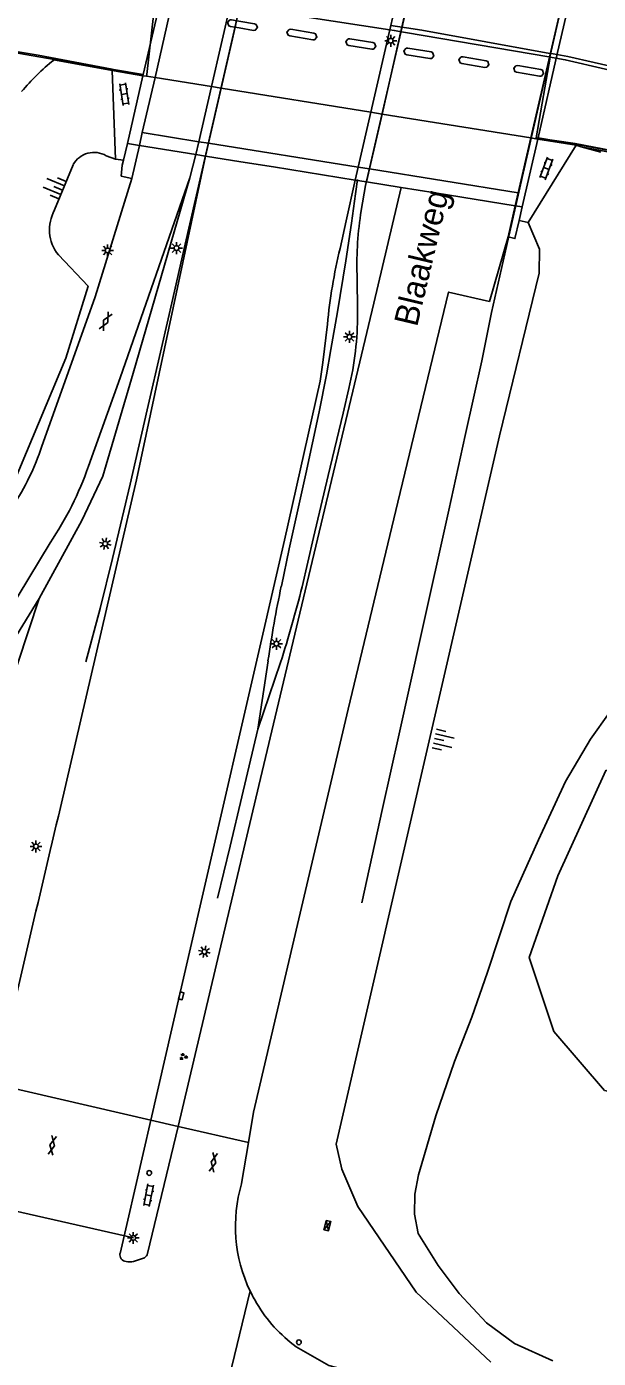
# Model space of a CAD drawing. Extents: x 131000 to 133013, y 393000 to 396501.
# Drawn here: x 131420.7 to 131480.6, y 394396 to 394535.6 of the extents above; entities that cross this region are included whole.
import ezdxf

# ---------------------------------------------------------------- set-up
doc = ezdxf.new("R2010")
doc.units = 0
for name, color, linetype in [('gg-anno-openbare ruimte label', 7, 'Continuous'), ('gg-knt-BGT kruinlijn', 7, 'Continuous'), ('gg-knt-bovenkant onderkant talud', 7, 'Continuous'), ('gg-knt-bronhoudergrens', 7, 'Continuous'), ('gg-knt-verharding', 7, 'Continuous'), ('gg-knt-verharding niveau 01', 7, 'Continuous'), ('gg-knt-verharding nz', 7, 'Continuous'), ('gg-kwrk-duiker nz buis', 7, 'Continuous'), ('gg-kwrk-kunstwerk', 7, 'Continuous'), ('gg-kwrk-kunstwerk niveau 01', 7, 'Continuous'), ('gt-grn-groengrens', 7, 'Continuous'), ('gt-grn-weggrens', 7, 'Continuous'), ('gt-knt-geleideconstructie', 7, 'Continuous'), ('gt-knt-lijn portaal', 7, 'Continuous'), ('gt-symb-gesloten verharding', 7, 'Continuous'), ('gt-symb-groenvak', 7, 'Continuous'), ('gt-symb-klinker verharding', 7, 'Continuous'), ('gt-symb-kolk', 7, 'Continuous'), ('gt-symb-lichtmast', 7, 'Continuous'), ('gt-symb-talud symbool', 7, 'Continuous'), ('gt-symb-verkeersregelinstallatiekast', 7, 'Continuous'), ('gt-symb-verkeersregelinstallatiepaal', 7, 'Continuous'), ('gx-grn-maaiveld', 7, 'Continuous')]:
    doc.layers.add(name, color=color, linetype=linetype)

# ---------------------------------------------------------------- blocks, each defined once
blk = doc.blocks.new('gt0-LMAST')
at = {"layer": 'gt-symb-lichtmast'}
for p, q in [((-0.18, 0.17), (-0.45, 0.44)), ((-0.01, 0.25), (-0.01, 0.62)), ((0.17, 0.17), (0.44, 0.44)), ((-0.26, 0), (-0.63, 0)), ((-0.18, -0.18), (-0.45, -0.45)), ((-0.01, -0.25), (-0.01, -0.63)), ((0.44, -0.45), (0.17, -0.18)), ((0.24, 0), (0.62, 0))]:
    blk.add_line(p, q, dxfattribs=at)
blk.add_circle((-0.01, 0), 0.25, dxfattribs=at)
blk = doc.blocks.new('gt0-KL1')
at = {"layer": 'gt-symb-klinker verharding'}
for p, q in [((-1.15, 0.3), (1.15, 0.3)), ((-1, -0.3), (-1, 0.3)), ((-0.5, 0.3), (-0.5, 0.45)), ((0, -0.3), (0, 0.3)), ((0.5, 0.3), (0.5, 0.45)), ((1, -0.3), (1, 0.3)), ((-1.15, -0.3), (1.15, -0.3)), ((-0.5, -0.45), (-0.5, -0.3)), ((0.5, -0.45), (0.5, -0.3))]:
    blk.add_line(p, q, dxfattribs=at)
blk = doc.blocks.new('gt0-GESVH1')
at = {"layer": 'gt-symb-gesloten verharding'}
for p, q in [((-0.99, -0.26), (0.01, 0.24)), ((0.01, -0.26), (-0.99, 0.24)), ((0.01, 0.24), (1.01, -0.26)), ((1.01, 0.24), (0.01, -0.26))]:
    blk.add_line(p, q, dxfattribs=at)
blk = doc.blocks.new('gt0-TALUD_1')
at = {"layer": 'gt-symb-talud symbool'}
for p, q in [((-1, -1), (-1, 0)), ((-0.5, -2), (-0.5, 0)), ((0, -1), (0, 0)), ((0.5, -2), (0.5, 0)), ((1, -1), (1, 0))]:
    blk.add_line(p, q, dxfattribs=at)
blk = doc.blocks.new('gt0-VIPAAL')
at = {"layer": 'gt-symb-verkeersregelinstallatiepaal'}
blk.add_circle((0, 0), 0.25, dxfattribs=at)
blk = doc.blocks.new('gt0-VRIKST')
at = {"layer": 'gt-symb-verkeersregelinstallatiekast'}
for p, q in [((-0.5, -0.25), (0.5, 0.25)), ((-0.5, 0.25), (0.5, -0.25))]:
    blk.add_line(p, q, dxfattribs=at)
blk.add_lwpolyline([(0.5, 0.25), (-0.5, 0.25), (-0.5, -0.25), (0.5, -0.25)], close=True, dxfattribs=at)
blk = doc.blocks.new('gt0-GRVAK')
at = {"layer": 'gt-symb-groenvak'}
for p, q in [((-0.11, 0.19), (-0.23, 0.24)), ((-0.18, 0.15), (0.09, 0.15)), ((-0.09, 0.21), (-0.16, 0.32)), ((-0.05, 0.21), (-0.05, 0.39)), ((0, 0.21), (0.06, 0.32)), ((0.02, 0.19), (0.13, 0.24)), ((0.26, -0.05), (0.2, 0.06)), ((0.31, -0.05), (0.31, 0.13)), ((0.35, -0.05), (0.41, 0.06)), ((-0.24, -0.23), (-0.36, -0.18)), ((-0.32, -0.26), (-0.05, -0.26)), ((-0.23, -0.21), (-0.29, -0.09)), ((-0.18, -0.2), (-0.18, -0.02)), ((-0.14, -0.21), (-0.07, -0.09)), ((-0.12, -0.23), (0, -0.18)), ((0.24, -0.07), (0.12, -0.02)), ((0.17, -0.11), (0.44, -0.11)), ((0.37, -0.07), (0.49, -0.02))]:
    blk.add_line(p, q, dxfattribs=at)
blk = doc.blocks.new('gt0-KOLK')
at = {"layer": 'gt-symb-kolk'}
blk.add_lwpolyline([(0, 0), (0.37, 0), (0.37, 0.4), (-0.38, 0.4), (-0.38, 0), (0, 0)], dxfattribs=at)

msp = doc.modelspace()

# ---------------------------------------------------------------- linework, layer by layer
at = {"layer": 'gg-knt-BGT kruinlijn'}
for p, q in [((131429.05, 394522.08), (131430.04, 394521.73)), ((131423.65, 394516.39), (131425.6, 394521.14)), ((131470.29, 394492.7), (131453.14, 394418.48)), ((131422.02, 394475.65), (131412.64, 394447.29)), ((131469.38, 394395.62), (131461.54, 394402.95))]:
    msp.add_line(p, q, dxfattribs=at)
for points in [[(131473.27, 394515.09), (131474.45, 394512.29), (131474.43, 394509.76), (131470.29, 394492.7)], [(131383.88, 394437.84), (131395.29, 394451.29), (131407.22, 394467.55), (131417.8, 394484.14), (131424.83, 394500.87), (131427.16, 394508.4), (131424.04, 394511.69)], [(131461.54, 394402.95), (131455.41, 394411.93), (131453.74, 394415.83), (131453.14, 394418.48)]]:
    msp.add_lwpolyline(points, dxfattribs=at)
for centre, radius, start, end in [((131427.78, 394519.94), 2.49, 59.2969, 151.084), ((131427.34, 394514.33), 4.23, 150.8617, 218.6757)]:
    msp.add_arc(centre, radius, start, end, dxfattribs=at)
at = {"layer": 'gg-knt-bovenkant onderkant talud'}
msp.add_line((131423.54, 394532.12), (131429.68, 394531), dxfattribs=at)
msp.add_lwpolyline([(131437.81, 394519.77), (131431.89, 394499.29), (131428.71, 394488.5), (131426.49, 394483.84), (131422.02, 394475.65)], dxfattribs=at)
msp.add_arc((131438.96, 394513.13), 24.45, 129.074, 140.1537, dxfattribs=at)
at = {"layer": 'gg-knt-bronhoudergrens'}
msp.add_lwpolyline([(131405.47, 394535.24), (131409.11, 394534.78), (131413.08, 394534.1), (131421.91, 394532.63), (131429.68, 394531.15), (131429.68, 394531)], dxfattribs=at)
at = {"layer": 'gg-knt-verharding'}
for p, q in [((131432.91, 394530.47), (131429.68, 394531)), ((131429.68, 394531), (131430.04, 394521.73)), ((131473.27, 394515.09), (131478.32, 394523.17)), ((131478.32, 394523.17), (131474.29, 394523.83)), ((131430.04, 394521.73), (131430.86, 394521.6)), ((131432.23, 394488.09), (131439.45, 394522.04)), ((131438.46, 394522.2), (131437.81, 394519.77)), ((131472.32, 394515.28), (131473.27, 394515.09)), ((131424.25, 394453.76), (131432.23, 394488.09)), ((131423.17, 394481.51), (131413.49, 394465.45)), ((131433.73, 394420.99), (131430.5, 394407.02)), ((131433.73, 394420.99), (131436.58, 394420.33)), ((131433.39, 394407.01), (131436.58, 394420.33)), ((131443.96, 394418.63), (131443.25, 394414.33)), ((131431.91, 394406.17), (131433.06, 394406.55))]:
    msp.add_line(p, q, dxfattribs=at)
for points in [[(131422.45, 394492.03), (131427.88, 394507.29), (131431.74, 394519.69)], [(131437.81, 394519.77), (131430.53, 394498.78), (131427.19, 394489.52)], [(131459.96, 394518.76), (131457.1, 394506.64), (131449.19, 394473.39), (131445.23, 394456.81), (131441.06, 394439.25), (131436.58, 394420.33)], [(131455.15, 394519.52), (131454.2, 394515.26), (131453.56, 394512.36)], [(131471.18, 394513.56), (131469.21, 394506.8), (131464.93, 394507.78), (131459.61, 394485.77), (131454.43, 394464.07), (131449.23, 394442.1), (131444.49, 394421.83), (131443.96, 394418.63)], [(131433.73, 394420.99), (131436.72, 394434.05), (131447.73, 394481.77), (131451.47, 394498.44), (131451.77, 394500.41), (131452.24, 394504.41)], [(131448.96, 394397.23), (131452.4, 394395.25), (131459.3, 394393.44)]]:
    msp.add_lwpolyline(points, dxfattribs=at)
for centre, radius, start, end in [((131508.14, 394499.17), 56.15, 166.4167, 174.6517), ((131397, 394500.04), 26.68, 327.4924, 342.5392), ((131395.02, 394500.65), 34.04, 325.7927, 340.9229), ((134415.36, 393744.36), 3074.08, 166.65758, 167.21315), ((131458.35, 394409.86), 15.75, 163.5297, 205.5356), ((131431.21, 394406.89), 0.727, 169.5914, 264.9801), ((131432.72, 394407.15), 0.681, 299.2665, 348.2912), ((131431.51, 394407.77), 1.65, 257.1884, 283.8656), ((131458.27, 394409.83), 15.66, 205.5256, 210.9341), ((131458.36, 394409.88), 15.77, 210.9484, 233.4006)]:
    msp.add_arc(centre, radius, start, end, dxfattribs=at)
at = {"layer": 'gg-knt-verharding niveau 01'}
for p, q in [((131458.84, 394535.58), (131461.6, 394547.61)), ((131462.77, 394547.42), (131460.01, 394535.4)), ((131442.13, 394538.13), (131440.1, 394529.32)), ((131441.09, 394529.16), (131442.56, 394535.56)), ((131442.56, 394535.56), (131442.71, 394536.24)), ((131456.79, 394526.64), (131458.84, 394535.58)), ((131460.01, 394535.4), (131457.96, 394526.45)), ((131440.1, 394529.32), (131438.77, 394523.55)), ((131439.76, 394523.39), (131441.09, 394529.16)), ((131455.46, 394520.88), (131456.79, 394526.64)), ((131457.96, 394526.45), (131456.64, 394520.69)), ((131438.77, 394523.55), (131438.46, 394522.2)), ((131439.45, 394522.04), (131439.76, 394523.39)), ((131455.15, 394519.52), (131455.46, 394520.88)), ((131456.64, 394520.69), (131456.32, 394519.34))]:
    msp.add_line(p, q, dxfattribs=at)
at = {"layer": 'gg-knt-verharding nz'}
for p, q in [((131434.17, 394530.27), (131440.1, 394529.32)), ((131440.1, 394529.32), (131441.09, 394529.16)), ((131441.09, 394529.16), (131456.79, 394526.64)), ((131456.79, 394526.64), (131457.96, 394526.45)), ((131457.96, 394526.45), (131473.57, 394523.95))]:
    msp.add_line(p, q, dxfattribs=at)
at = {"layer": 'gg-kwrk-duiker nz buis'}
for p, q in [((131405.04, 394535.33), (131423.61, 394532.17)), ((131423.61, 394532.17), (131432.93, 394530.58))]:
    msp.add_line(p, q, dxfattribs=at)
msp.add_lwpolyline([(131474.32, 394523.97), (131478.24, 394523.3), (131489.42, 394521.19)], dxfattribs=at)
at = {"layer": 'gg-kwrk-kunstwerk'}
for p, q in [((131438.77, 394523.55), (131432.84, 394524.5)), ((131431.27, 394523.35), (131430.86, 394521.6)), ((131432.53, 394523.15), (131431.74, 394519.69)), ((131439.76, 394523.39), (131438.77, 394523.55)), ((131455.46, 394520.88), (131439.76, 394523.39)), ((131456.64, 394520.69), (131455.46, 394520.88)), ((131472.24, 394518.19), (131456.64, 394520.69)), ((131471.18, 394513.56), (131471.93, 394516.84)), ((131472.65, 394516.72), (131472.32, 394515.28))]:
    msp.add_line(p, q, dxfattribs=at)
for points in [[(131431.74, 394519.69), (131430.63, 394519.95), (131430.74, 394521.08), (131430.86, 394521.6)], [(131472.32, 394515.28), (131471.89, 394513.4), (131471.18, 394513.56)]]:
    msp.add_lwpolyline(points, dxfattribs=at)
at = {"layer": 'gg-kwrk-kunstwerk niveau 01'}
for p, q in [((131475.66, 394533.01), (131478.39, 394544.86)), ((131479.1, 394544.74), (131476.37, 394532.9)), ((131434.8, 394538.68), (131432.93, 394530.58)), ((131435.66, 394536.76), (131434.17, 394530.27)), ((131473.57, 394523.95), (131475.66, 394533.01)), ((131476.37, 394532.9), (131474.29, 394523.83)), ((131432.91, 394530.47), (131431.27, 394523.35)), ((131434.17, 394530.27), (131432.84, 394524.5)), ((131432.93, 394530.58), (131432.91, 394530.47)), ((131432.84, 394524.5), (131432.53, 394523.15)), ((131432.53, 394523.15), (131431.27, 394523.35)), ((131438.46, 394522.2), (131432.53, 394523.15)), ((131472.24, 394518.19), (131473.57, 394523.95)), ((131474.29, 394523.83), (131472.65, 394516.72)), ((131439.45, 394522.04), (131438.46, 394522.2)), ((131443.18, 394521.44), (131439.45, 394522.04)), ((131446.6, 394520.9), (131443.18, 394521.44)), ((131455.15, 394519.52), (131446.6, 394520.9)), ((131456.32, 394519.34), (131455.15, 394519.52)), ((131459.96, 394518.76), (131456.32, 394519.34)), ((131463.53, 394518.18), (131459.96, 394518.76)), ((131471.93, 394516.84), (131463.53, 394518.18)), ((131471.93, 394516.84), (131472.24, 394518.19)), ((131471.93, 394516.84), (131472.65, 394516.72))]:
    msp.add_line(p, q, dxfattribs=at)
at = {"layer": 'gt-grn-groengrens'}
msp.add_lwpolyline([(131422.02, 394475.65), (131407.25, 394451.6), (131389.92, 394430.41), (131384.61, 394418.87)], dxfattribs=at)
at = {"layer": 'gt-grn-weggrens'}
for p, q in [((131433.73, 394420.99), (131417.51, 394424.73)), ((131436.58, 394420.33), (131443.96, 394418.63)), ((131444.14, 394403.08), (131439.96, 394385.76))]:
    msp.add_line(p, q, dxfattribs=at)
at = {"layer": 'gt-knt-geleideconstructie'}
for p, q in [((131455.39, 394505.52), (131455.34, 394509.61)), ((131444.93, 394461.97), (131446.02, 394469.14)), ((131444.93, 394461.97), (131447.32, 394468.95))]:
    msp.add_line(p, q, dxfattribs=at)
for points in [[(131465.64, 394656.53), (131464.33, 394645.42), (131463.66, 394640.15), (131462.78, 394633.62), (131461.7, 394627.04), (131460.47, 394619.16), (131459.39, 394612.58), (131458.15, 394606), (131457.27, 394600.74), (131456.21, 394595.53), (131455.11, 394590.32), (131453.78, 394584.5), (131448.08, 394559.79), (131444.51, 394544.19), (131438.99, 394520.12), (131437.21, 394512.35), (131436.05, 394507.12), (131434.86, 394501.94), (131433.36, 394495.44), (131431.56, 394487.64), (131429.71, 394479.86), (131428.41, 394474.6), (131426.93, 394469.04)], [(131455.77, 394516.32), (131456.23, 394518.95), (131456.68, 394520.9), (131465.06, 394557.27), (131471.79, 394586.44), (131472.64, 394590.4), (131473.45, 394595.65), (131474.24, 394600.96)], [(131455.84, 394443.78), (131458, 394453.64), (131459.76, 394461.49), (131460.92, 394466.7), (131462.06, 394471.89), (131464.95, 394484.93), (131466.67, 394492.74), (131468.41, 394500.57), (131469.45, 394505.64), (131472.74, 394520.26), (131478.46, 394545.1)], [(131447.41, 394476.97), (131448.22, 394480.88), (131449.96, 394488.72), (131451.36, 394495.24), (131452.13, 394499.12), (131452.59, 394501.78), (131453.28, 394505.73), (131454.16, 394511.05), (131454.77, 394515.02), (131455.19, 394518.08), (131455.4, 394519.59)], [(131449.59, 394476.9), (131450.77, 394482.06), (131452.31, 394488.55), (131453.89, 394495.08), (131454.48, 394497.69)], [(131440.73, 394444.26), (131442.03, 394449.72), (131443.28, 394454.88), (131444.93, 394461.97)]]:
    msp.add_lwpolyline(points, dxfattribs=at)
for centre, radius, start, end in [((131491.34, 394510.65), 36.01, 170.9431, 181.6544), ((131422.66, 394505.38), 32.74, 346.4195, 0.2449), ((131586.65, 394448.2), 142.19, 168.3269, 171.5302), ((131321.54, 394509.11), 132.04, 342.2952, 345.8826)]:
    msp.add_arc(centre, radius, start, end, dxfattribs=at)
at = {"layer": 'gt-knt-lijn portaal'}
msp.add_line((131431.9, 394408.64), (131413.07, 394412.94), dxfattribs=at)
at = {"layer": 'gx-grn-maaiveld'}
for p, q in [((131433.28, 394530.41), (131432.91, 394530.47)), ((131433.28, 394530.41), (131434.17, 394530.27)), ((131473.57, 394523.95), (131474.1, 394523.86)), ((131474.1, 394523.86), (131474.11, 394523.97)), ((131474.1, 394523.86), (131474.29, 394523.83)), ((131478.32, 394523.17), (131478.83, 394523.02))]:
    msp.add_line(p, q, dxfattribs=at)
for points in [[(131434.27, 394538.99), (131433.31, 394530.59), (131433.3, 394530.54), (131433.28, 394530.41)], [(131475.59, 394532.41), (131475.45, 394532.43), (131460.41, 394535.01), (131459.24, 394535.21), (131458.79, 394535.28), (131443.49, 394537.6), (131442.05, 394537.81), (131435.89, 394538.75), (131435.2, 394538.85), (131434.68, 394538.93), (131434.27, 394538.99)], [(131442, 394536.31), (131442.18, 394536.32), (131443.15, 394536.16), (131444.6, 394535.92), (131444.77, 394535.85), (131444.91, 394535.51), (131444.67, 394535.23), (131444.49, 394535.22), (131442.99, 394535.47), (131442.07, 394535.62), (131441.9, 394535.69), (131441.76, 394536.04), (131442, 394536.31)], [(131448.22, 394535.32), (131448.41, 394535.33), (131450.82, 394534.93), (131450.99, 394534.86), (131451.13, 394534.51), (131450.89, 394534.24), (131450.71, 394534.23), (131448.29, 394534.63), (131448.12, 394534.7), (131447.99, 394535.04), (131448.22, 394535.32)], [(131458.9, 394535.74), (131460.52, 394535.49), (131462.13, 394535.23), (131475.54, 394532.81), (131475.66, 394532.79), (131475.89, 394532.75), (131477.42, 394532.47), (131482.96, 394531.21), (131489.48, 394529.63), (131495.87, 394527.94), (131507.28, 394524.86), (131520.85, 394520.86), (131530.33, 394517.85), (131533.69, 394516.46), (131536.2, 394515.36), (131538.9, 394514.15), (131543.31, 394511.99)], [(131454.4, 394534.33), (131454.59, 394534.34), (131457.01, 394533.94), (131457.18, 394533.87), (131457.31, 394533.52), (131457.07, 394533.25), (131456.89, 394533.24), (131454.47, 394533.64), (131454.3, 394533.71), (131454.17, 394534.05), (131454.4, 394534.33)], [(131460.5, 394533.35), (131460.68, 394533.36), (131463.1, 394532.96), (131463.27, 394532.89), (131463.4, 394532.54), (131463.17, 394532.27), (131462.98, 394532.26), (131460.57, 394532.66), (131460.39, 394532.72), (131460.26, 394533.07), (131460.5, 394533.35)], [(131466.27, 394532.43), (131466.45, 394532.44), (131468.87, 394532.04), (131469.04, 394531.97), (131469.17, 394531.62), (131468.93, 394531.35), (131468.75, 394531.34), (131466.33, 394531.74), (131466.16, 394531.81), (131466.03, 394532.15), (131466.27, 394532.43)], [(131471.99, 394531.51), (131472.18, 394531.52), (131474.59, 394531.12), (131474.77, 394531.05), (131474.9, 394530.71), (131474.66, 394530.43), (131474.48, 394530.42), (131472.06, 394530.82), (131471.89, 394530.89), (131471.76, 394531.24), (131471.99, 394531.51)], [(131474.11, 394523.97), (131474.89, 394528.4), (131475.59, 394532.41)], [(131475.59, 394532.41), (131475.8, 394532.37), (131477.16, 394532.14), (131485.61, 394530.17), (131491.75, 394528.62), (131502.23, 394525.55), (131521.97, 394519.99), (131528.95, 394517.83), (131531.24, 394516.94), (131533.23, 394516.05), (131535.34, 394515.13), (131543.14, 394511.63), (131543.31, 394511.99)], [(131474.11, 394523.97), (131478.2, 394523.35), (131489.06, 394521.28), (131489.02, 394521.08), (131478.83, 394523.02)], [(131480.89, 394522.44), (131478.83, 394523.02)], [(131475.85, 394395.77), (131471.85, 394397.56), (131468.92, 394399.74), (131466.04, 394402.83), (131463.85, 394405.76), (131461.74, 394409.1), (131461.37, 394411.13), (131461.4, 394413.22), (131461.77, 394415.27), (131463.6, 394421.44), (131465.57, 394427.15), (131467.39, 394431.79), (131469.03, 394436.51), (131471.48, 394443.89), (131474.35, 394450.37), (131477.2, 394456.49), (131479.82, 394460.91), (131483.8, 394466.51)], [(131499.91, 394439.78), (131490.4, 394453.65), (131484.15, 394457.97), (131481.43, 394457.64), (131476.38, 394446.61), (131473.39, 394438.05), (131475.98, 394430.26), (131481.29, 394424.09), (131483.66, 394423.59), (131496.76, 394430.31), (131500.25, 394437.81), (131499.91, 394439.78)]]:
    msp.add_lwpolyline(points, dxfattribs=at)

# ---------------------------------------------------------------- block references
at = {"layer": 'gt-symb-gesloten verharding'}
for p, rotation in [((131428.99, 394504.71), 62.537772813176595), ((131423.41, 394418.35), -101.24252570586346), ((131440.3, 394416.57), -101.24252570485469)]:
    msp.add_blockref('gt0-GESVH1', p, dxfattribs=dict(at, rotation=rotation))
at = {"layer": 'gt-symb-groenvak'}
msp.add_blockref('gt0-GRVAK', (131437.12, 394427.63), dxfattribs=at)
at = {"layer": 'gt-symb-klinker verharding'}
for p, rotation in [((131430.94, 394528.54), 98.74616226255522), ((131475.19, 394520.75), 69.15573557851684), ((131433.5, 394413.11), -101.24252570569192)]:
    msp.add_blockref('gt0-KL1', p, dxfattribs=dict(at, rotation=rotation))
at = {"layer": 'gt-symb-kolk', "rotation": -102.99885084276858}
msp.add_blockref('gt0-KOLK', (131436.72, 394434.05), dxfattribs=at)
at = {"layer": 'gt-symb-lichtmast'}
for p in [(131458.88, 394534.13), (131436.43, 394512.4), (131429.21, 394512.15), (131454.56, 394503.09), (131446.9, 394470.93), (131421.7, 394449.68), (131431.9, 394408.64)]:
    msp.add_blockref('gt0-LMAST', p, dxfattribs=at)
for p, rotation in [((131428.95, 394481.41), 77.06118937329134), ((131439.35, 394438.63), -103.00750479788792)]:
    msp.add_blockref('gt0-LMAST', p, dxfattribs=dict(at, rotation=rotation))
at = {"layer": 'gt-symb-talud symbool'}
for p, xscale, yscale, rotation in [((131424.48, 394518.47), 0.9996924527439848, 0.9996924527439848, -112.5890038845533), ((131463.46, 394460.99), 0.9996504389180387, 0.9996504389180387, 76.99249520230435)]:
    msp.add_blockref('gt0-TALUD_1', p, dxfattribs=dict(at, xscale=xscale, yscale=yscale, rotation=rotation))
at = {"layer": 'gt-symb-verkeersregelinstallatiekast', "rotation": 77.0265525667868}
msp.add_blockref('gt0-VRIKST', (131452.23, 394409.93), dxfattribs=at)
at = {"layer": 'gt-symb-verkeersregelinstallatiepaal'}
for p, rotation in [((131433.56, 394415.45), -102.97344743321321), ((131449.25, 394397.7), -102.97344743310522)]:
    msp.add_blockref('gt0-VIPAAL', p, dxfattribs=dict(at, rotation=rotation))

# ---------------------------------------------------------------- texts
at = {"layer": 'gg-anno-openbare ruimte label'}
msp.add_text('Blaakweg', height=2.5, rotation=76.6, dxfattribs=at).set_placement((131461.63, 394504.06))

doc.saveas('drawing.dxf')
